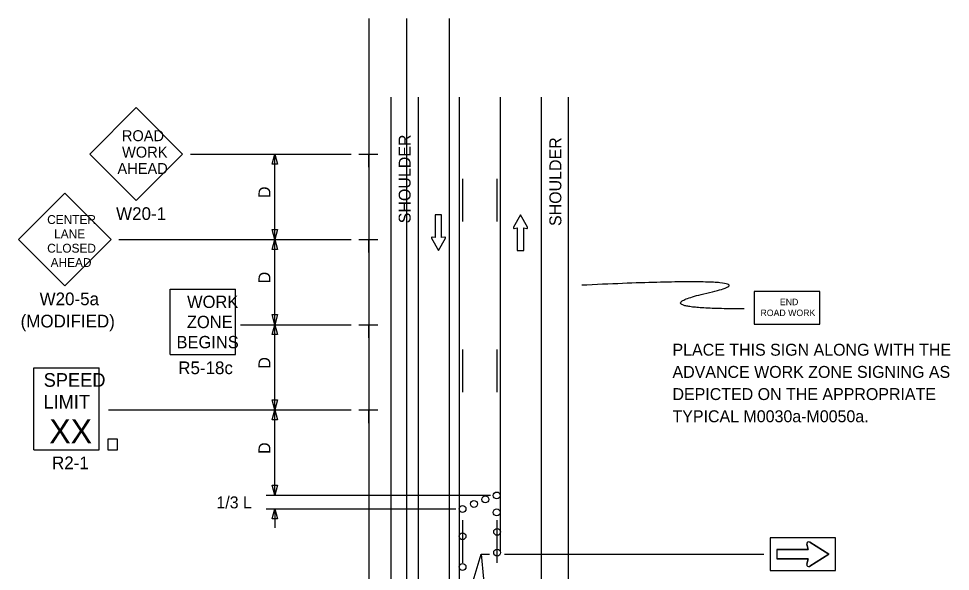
# Model space of a CAD drawing. Extents: x 16748 to 18296, y 7218 to 8262.
# Drawn here: x 16783 to 17329, y 7938 to 8262 of the extents above; entities that cross this region are included whole.
import ezdxf

# ---------------------------------------------------------------- set-up
doc = ezdxf.new("R2010")
doc.units = 0
for name, color, linetype in [('BORDER', 7, 'Continuous'), ('MT_SCRATCH_LEVEL_A', 7, 'Continuous'), ('MT_SCRATCH_LEVEL_E', 7, 'Continuous'), ('PAVT_EDGE_EX', 7, 'Continuous'), ('TRAFFIC_SIGNS_PR', 7, 'Continuous'), ('TYPICAL_EX', 7, 'Continuous'), ('TYPICAL_TEXT_DIMEN_EX', 7, 'Continuous'), ('TYPICAL_TEXT_DIMEN_PR', 7, 'Continuous')]:
    doc.layers.add(name, color=color, linetype=linetype)

msp = doc.modelspace()

# ---------------------------------------------------------------- linework, layer by layer
at = {"layer": 'BORDER'}
for p, q in [((17017.08, 8216.25), (17017.08, 7341.25)), ((17089.08, 8216.25), (17089.08, 7765.38))]:
    msp.add_line(p, q, dxfattribs=at)
at = {"layer": 'MT_SCRATCH_LEVEL_A'}
for p, q in [((17041.08, 8216.25), (17041.08, 7341.25)), ((17065.08, 8216.25), (17065.08, 7950.29))]:
    msp.add_line(p, q, dxfattribs=at)
for points in [[(17043.08, 8168.47), (17043.08, 8143.47)], [(17063.08, 8168.47), (17063.08, 8143.47)], [(17043.08, 8068.47), (17043.08, 8043.47)], [(17063.08, 8068.47), (17063.08, 8043.47)], [(17043.08, 7968.47), (17043.08, 7943.47)], [(17063.08, 7968.47), (17063.08, 7943.47)]]:
    msp.add_lwpolyline(points, dxfattribs=at)
at = {"layer": 'MT_SCRATCH_LEVEL_E'}
for p, q in [((17030.82, 8147.27), (17027.08, 8147.27)), ((17027.08, 8147.27), (17027.08, 8134.01)), ((17030.82, 8147.27), (17027.08, 8147.27)), ((17027.08, 8147.27), (17027.08, 8134.01)), ((17030.82, 8134.01), (17030.82, 8147.27)), ((17030.82, 8134.01), (17030.82, 8147.27)), ((17077.02, 8147.29), (17072.9, 8140.05)), ((17077.02, 8147.29), (17072.9, 8140.05)), ((17081.16, 8140.05), (17077.02, 8147.29)), ((17081.16, 8140.05), (17077.02, 8147.29)), ((17073.39, 8139.36), (17075.16, 8139.68)), ((17073.39, 8139.36), (17075.16, 8139.68)), ((17075.16, 8139.68), (17075.16, 8126.42)), ((17075.16, 8139.68), (17075.16, 8126.42)), ((17078.91, 8126.42), (17078.91, 8139.68)), ((17078.91, 8139.68), (17080.68, 8139.36)), ((17078.91, 8126.42), (17078.91, 8139.68)), ((17078.91, 8139.68), (17080.68, 8139.36)), ((17027.08, 8134.01), (17025.3, 8134.32)), ((17027.08, 8134.01), (17025.3, 8134.32)), ((17032.6, 8134.32), (17030.82, 8134.01)), ((17032.6, 8134.32), (17030.82, 8134.01)), ((17024.82, 8133.64), (17028.97, 8126.4)), ((17024.82, 8133.64), (17028.97, 8126.4)), ((17028.97, 8126.4), (17033.08, 8133.64)), ((17028.97, 8126.4), (17033.08, 8133.64)), ((17075.16, 8126.42), (17078.91, 8126.42)), ((17075.16, 8126.42), (17078.91, 8126.42))]:
    msp.add_line(p, q, dxfattribs=at)
for centre, start, end in [((17073.31, 8139.82), 150.4248, 279.9638), ((17073.31, 8139.82), 150.4248, 279.9638), ((17080.75, 8139.82), 260.0362, 29.7731), ((17080.75, 8139.82), 260.0362, 29.7731), ((17025.23, 8133.86), 80.0362, 209.7731), ((17025.23, 8133.86), 80.0362, 209.7731), ((17032.67, 8133.86), 330.4248, 99.9638), ((17032.67, 8133.86), 330.4248, 99.9638)]:
    msp.add_arc(centre, 0.463, start, end, dxfattribs=at)
at = {"layer": 'PAVT_EDGE_EX'}
for p, q in [((16988.15, 8262.34), (16988.15, 7433.15)), ((17010.15, 8262.34), (17010.15, 7433.15)), ((17035.15, 8262.34), (17035.15, 7433.15)), ((17001.08, 8216.25), (17001.08, 7341.25)), ((17105.08, 8216.25), (17105.08, 7341.25))]:
    msp.add_line(p, q, dxfattribs=at)
at = {"layer": 'TRAFFIC_SIGNS_PR'}
for p, q in [((16851.77, 8210.16), (16824.59, 8182.97)), ((16878.96, 8182.97), (16851.77, 8210.16)), ((16824.59, 8182.97), (16851.77, 8155.79)), ((16851.77, 8155.79), (16878.96, 8182.97)), ((16809.95, 8160.13), (16782.8, 8132.97)), ((16837.1, 8132.97), (16809.95, 8160.13)), ((16782.8, 8132.97), (16809.95, 8105.82)), ((16809.95, 8105.82), (16837.1, 8132.97)), ((16871.56, 8065.4), (16871.56, 8103.8)), ((16871.56, 8103.8), (16909.96, 8103.8)), ((16909.96, 8065.4), (16909.96, 8103.8)), ((16871.56, 8065.4), (16909.96, 8065.4)), ((16791.69, 8057.7), (16830.09, 8057.7)), ((16791.69, 8009.7), (16791.69, 8057.7)), ((16830.09, 8009.7), (16830.09, 8057.7)), ((16791.69, 8009.7), (16830.09, 8009.7)), ((17245.78, 7951.23), (17244.94, 7954.29)), ((17246.62, 7955.53), (17257.78, 7948.43)), ((17227.38, 7951.23), (17245.78, 7951.23)), ((17227.38, 7951.23), (17227.38, 7945.63)), ((17257.78, 7948.43), (17246.62, 7941.33)), ((17245.78, 7945.63), (17227.38, 7945.63)), ((17244.94, 7942.57), (17245.78, 7945.63))]:
    msp.add_line(p, q, dxfattribs=at)
for points in [[(17214.13, 8083.24), (17252.53, 8083.24), (17252.53, 8102.44), (17214.13, 8102.44)], [(16835.11, 8009.7), (16840.7, 8009.7), (16840.7, 8015.87), (16835.11, 8015.87)], [(17223.38, 7938.83), (17261.78, 7938.83), (17261.78, 7958.03), (17223.38, 7958.03)]]:
    msp.add_lwpolyline(points, close=True, dxfattribs=at)
for points in [[(17244.94, 7954.29), (17245.78, 7951.23), (17227.38, 7951.23), (17227.38, 7945.63), (17245.78, 7945.63), (17244.94, 7942.57)], [(17246.62, 7941.33), (17257.78, 7948.43), (17246.62, 7955.53)]]:
    msp.add_lwpolyline(points, dxfattribs=at)
for centre in [(17056.41, 7980.58), (17063.08, 7982.88), (17043.08, 7974.97), (17049.75, 7977.87), (17063.08, 7972.94), (17043.08, 7958.97), (17063.32, 7961.52), (17063.32, 7949.37), (17043.08, 7940.97)]:
    msp.add_circle(centre, 2, dxfattribs=at)
for centre, start, end in [((17246.02, 7954.59), 57.5304, 195.3269), ((17246.02, 7954.59), 57.5304, 195.3269), ((17246.02, 7942.27), 164.6731, 302.4696), ((17246.02, 7942.27), 164.6731, 302.4696)]:
    msp.add_arc(centre, 1.12, start, end, dxfattribs=at)
msp.add_open_spline([(17208.17, 8092.23), (17145.53, 8092.23), (17230.55, 8111.57), (17112.93, 8106.08)], degree=2, dxfattribs=at)
at = {"layer": 'TYPICAL_EX'}
for p, q in [((16982.23, 8182.97), (16993.48, 8182.97)), ((16987.86, 8182.97), (16987.86, 8175.19)), ((16982.23, 8132.97), (16993.48, 8132.97)), ((16987.86, 8132.97), (16987.86, 8125.19)), ((16982.23, 8082.97), (16993.48, 8082.97)), ((16987.86, 8082.97), (16987.86, 8075.19)), ((16982.23, 8032.97), (16993.48, 8032.97)), ((16987.86, 8032.97), (16987.86, 8025.19))]:
    msp.add_line(p, q, dxfattribs=at)
at = {"layer": 'TYPICAL_TEXT_DIMEN_PR'}
for p, q in [((16883.54, 8182.97), (16977.71, 8182.97)), ((16931.41, 8177.11), (16932.98, 8182.97)), ((16932.98, 8182.97), (16934.55, 8177.11)), ((16932.98, 8132.97), (16932.98, 8182.97)), ((16932.98, 8177.11), (16931.41, 8177.11)), ((16934.55, 8177.11), (16932.98, 8177.11)), ((16932.98, 8132.97), (16931.41, 8138.84)), ((16931.41, 8138.84), (16932.98, 8138.84)), ((16932.98, 8138.84), (16934.55, 8138.84)), ((16934.55, 8138.84), (16932.98, 8132.97)), ((16841.56, 8132.97), (16977.71, 8132.97)), ((16931.41, 8127.11), (16932.98, 8132.97)), ((16932.98, 8132.97), (16934.55, 8127.11)), ((16932.98, 8082.97), (16932.98, 8132.97)), ((16932.98, 8127.11), (16931.41, 8127.11)), ((16934.55, 8127.11), (16932.98, 8127.11)), ((16932.98, 8082.97), (16931.41, 8088.84)), ((16931.41, 8088.84), (16932.98, 8088.84)), ((16932.98, 8088.84), (16934.55, 8088.84)), ((16934.55, 8088.84), (16932.98, 8082.97)), ((16912.93, 8082.97), (16977.71, 8082.97)), ((16931.41, 8077.11), (16932.98, 8082.97)), ((16932.98, 8082.97), (16934.55, 8077.11)), ((16932.98, 8032.97), (16932.98, 8082.97)), ((16932.98, 8077.11), (16931.41, 8077.11)), ((16934.55, 8077.11), (16932.98, 8077.11)), ((16932.98, 8032.97), (16931.41, 8038.84)), ((16931.41, 8038.84), (16932.98, 8038.84)), ((16932.98, 7990.72), (16932.98, 8040.72)), ((16932.98, 8038.84), (16934.55, 8038.84)), ((16934.55, 8038.84), (16932.98, 8032.97)), ((16835.45, 8032.97), (16977.71, 8032.97)), ((16931.41, 8027.11), (16932.98, 8032.97)), ((16932.98, 8032.97), (16934.55, 8027.11)), ((16932.98, 8027.11), (16931.41, 8027.11)), ((16934.55, 8027.11), (16932.98, 8027.11)), ((16932.98, 7982.97), (16931.41, 7988.83)), ((16931.41, 7988.83), (16932.98, 7988.83)), ((16932.98, 7982.97), (16932.98, 7990.72)), ((16932.98, 7988.83), (16934.55, 7988.83)), ((16934.55, 7988.83), (16932.98, 7982.97)), ((16927.98, 7982.97), (17059.45, 7982.97)), ((16927.98, 7974.97), (17039.1, 7974.97)), ((16931.41, 7969.1), (16932.98, 7974.96)), ((16932.98, 7974.96), (16934.55, 7969.1)), ((16932.98, 7974.96), (16932.98, 7963.89)), ((16932.98, 7969.1), (16931.41, 7969.1)), ((16934.55, 7969.1), (16932.98, 7969.1)), ((17048.75, 7930.83), (17053.95, 7948.53)), ((17053.95, 7948.53), (17055.33, 7934.03)), ((17053.95, 7948.53), (17058.93, 7948.53)), ((17067.63, 7948.53), (17219.69, 7948.53))]:
    msp.add_line(p, q, dxfattribs=at)

# ---------------------------------------------------------------- texts
at = {"layer": 'TRAFFIC_SIGNS_PR'}
for s, height, p in [('ROAD', 6.408, (16843.31, 8190.52)), ('WORK', 6.408, (16843.41, 8180.9)), ('AHEAD', 6.408, (16840.72, 8171.29)), ('W20-1', 7.449, (16839.93, 8144.33)), ('CENTER', 5.2, (16799.53, 8141.98)), ('LANE', 5.2, (16803.61, 8133.58)), ('CLOSED', 5.2, (16799.53, 8125.18)), ('AHEAD', 5.2, (16801.56, 8116.78)), ('W20-5a', 7.44, (16795.09, 8094.38)), ('WORK', 7.217, (16881.56, 8092.76)), ('END', 3.831, (17229.13, 8094.37)), ('ROAD WORK', 3.831, (17217.74, 8087.99)), ('(MODIFIED)', 7.44, (16783.95, 8081.34)), ('ZONE', 7.217, (16881.44, 8080.95)), ('BEGINS', 7.217, (16875.37, 8069.14)), ('PLACE THIS SIGN ALONG WITH THE', 7, (17166.16, 8064.78)), ('R5-18c', 7.44, (16876.37, 8053.96)), ('ADVANCE WORK ZONE SIGNING AS', 7, (17166.16, 8051.78)), ('SPEED', 8, (16797.46, 8046.56)), ('LIMIT', 8, (16797.3, 8033.76)), ('DEPICTED ON THE APPROPRIATE', 7, (17166.16, 8038.78)), ('TYPICAL M0030a-M0050a.', 7, (17166.16, 8025.78)), ('XX', 14.031, (16800.8, 8013.46)), ('R2-1', 7.44, (16802.37, 7998.26))]:
    msp.add_text(s, height=height, dxfattribs=at).set_placement(p)
at = {"layer": 'TYPICAL_TEXT_DIMEN_EX'}
for p in [(17012.63, 8142.4), (17101, 8140.79)]:
    msp.add_text('SHOULDER', height=7, rotation=90, dxfattribs=at).set_placement(p)
at = {"layer": 'TYPICAL_TEXT_DIMEN_PR'}
for p in [(16930.42, 8157.19), (16930.42, 8107.19), (16930.42, 8057.19), (16930.42, 8007.19)]:
    msp.add_text('D', height=7, rotation=90, dxfattribs=at).set_placement(p)
msp.add_text('1/3 L', height=7, dxfattribs=at).set_placement((16898.74, 7975.3))

doc.saveas('drawing.dxf')
